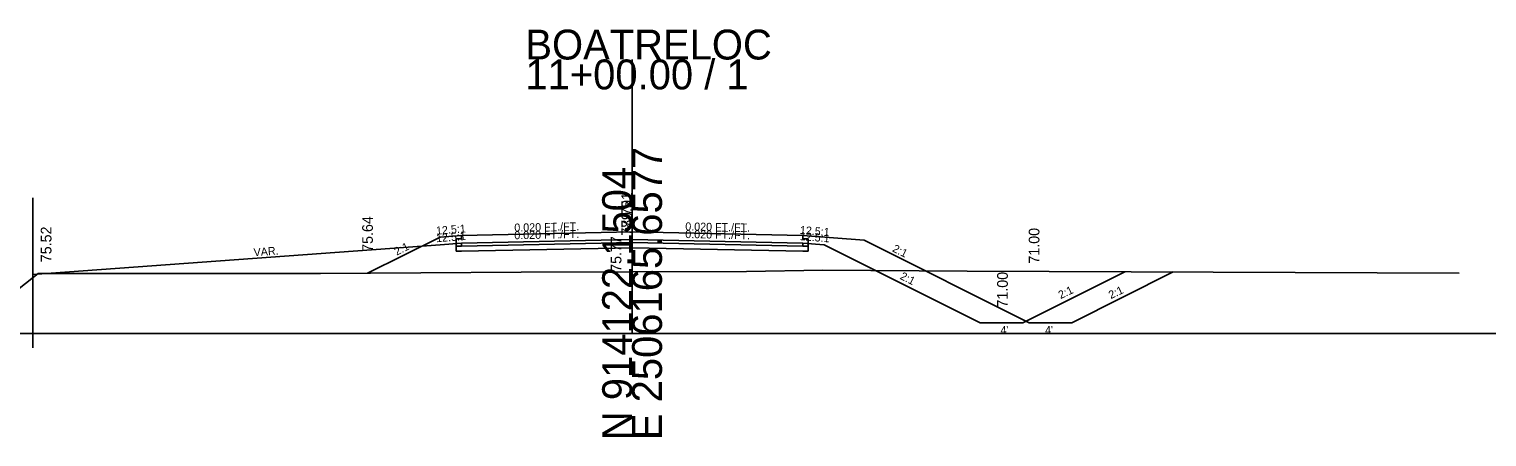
# Model space of a CAD drawing. Extents: x -26 to 403, y -10 to 2549.
# Drawn here: x 143.5 to 280.1, y 490.3 to 528.5 of the extents above; entities that cross this region are included whole.
import ezdxf

# ---------------------------------------------------------------- set-up
doc = ezdxf.new("R2010")
doc.units = 0
for name, color, linetype in [('RD_GPK_XS_Cell', 7, 'Continuous'), ('RD_Sketch9', 7, 'Continuous'), ('RD_XS_EarthShd', 7, 'Continuous'), ('RD_XS_ExGround', 7, 'Continuous'), ('RD_XS_Pave', 7, 'Continuous'), ('RD_XS_PaveOvlay', 7, 'Continuous'), ('RD_XS_TieSlope', 7, 'Continuous'), ('RD_XS_TX_Elev_EX', 7, 'Continuous'), ('RD_XS_TX_Elev_PR', 7, 'Continuous'), ('RD_XS_TX_ShdSlope', 7, 'Continuous'), ('RD_XS_TX_Slope', 7, 'Continuous')]:
    doc.layers.add(name, color=color, linetype=linetype)

msp = doc.modelspace()

# ---------------------------------------------------------------- linework, layer by layer
at = {"layer": 'RD_GPK_XS_Cell'}
for p, q in [((200, 500), (200, 525.67)), ((0, 500), (200, 500)), ((200, 500), (400, 500))]:
    msp.add_line(p, q, dxfattribs=at)
at = {"layer": 'RD_Sketch9'}
for p, q in [((182, 509.03), (175.21, 505.64)), ((184, 509.19), (182, 509.03)), ((183.5, 508.85), (184, 508.86)), ((183.5, 508.18), (183.5, 508.85)), ((184, 508.19), (183.5, 508.18)), ((184, 509.19), (200, 509.51)), ((184, 508.86), (184, 509.19)), ((184, 508.19), (200, 508.51)), ((200, 509.51), (216, 509.19)), ((200, 508.51), (216, 508.19)), ((216, 508.86), (216, 509.19)), ((216, 509.19), (221.74, 508.73)), ((216.5, 508.85), (216, 508.86)), ((216, 508.19), (216.5, 508.18)), ((216.5, 508.18), (216.5, 508.85)), ((221.74, 508.73), (237.2, 501)), ((250.71, 505.76), (241.2, 501)), ((237.2, 501), (241.2, 501))]:
    msp.add_line(p, q, dxfattribs=at)
at = {"layer": 'RD_XS_EarthShd'}
for p, q in [((184, 508.47), (182, 508.31)), ((216, 508.47), (218, 508.31))]:
    msp.add_line(p, q, dxfattribs=at)
at = {"layer": 'RD_XS_ExGround'}
for p, q in [((141.39, 503.28), (144.35, 505.6)), ((144.35, 505.6), (158.25, 505.6)), ((158.25, 505.6), (164.72, 505.6)), ((164.72, 505.6), (167.77, 505.61)), ((167.77, 505.61), (170.79, 505.61)), ((170.79, 505.61), (189.59, 505.73)), ((189.59, 505.73), (200, 505.77)), ((200, 505.77), (210.71, 505.81)), ((210.71, 505.81), (217.87, 505.92)), ((217.87, 505.92), (231.41, 505.84)), ((231.41, 505.84), (277.51, 505.64))]:
    msp.add_line(p, q, dxfattribs=at)
at = {"layer": 'RD_XS_Pave'}
for p, q in [((183.5, 508.18), (184, 508.19)), ((183.5, 507.7), (183.5, 508.18)), ((184, 508.19), (184, 508.47)), ((216, 508.19), (216, 508.47)), ((216.5, 508.18), (216, 508.19)), ((216.5, 507.7), (216.5, 508.18)), ((184, 507.71), (183.5, 507.7)), ((184, 507.71), (200, 508.03)), ((200, 508.03), (216, 507.71)), ((216, 507.71), (216.5, 507.7))]:
    msp.add_line(p, q, dxfattribs=at)
at = {"layer": 'RD_XS_PaveOvlay'}
for p, q in [((184, 508.47), (200, 508.79)), ((200, 508.79), (216, 508.47))]:
    msp.add_line(p, q, dxfattribs=at)
at = {"layer": 'RD_XS_TieSlope'}
for p, q in [((143.84, 498.64), (143.84, 512.72)), ((182, 508.31), (143.84, 505.52)), ((218, 508.31), (232.63, 501)), ((246.18, 505.77), (236.63, 501)), ((232.63, 501), (236.63, 501))]:
    msp.add_line(p, q, dxfattribs=at)

# ---------------------------------------------------------------- texts
at = {"layer": 'RD_GPK_XS_Cell'}
for s, p in [('BOATRELOC', (190, 525.67)), ('11+00.00 / 1', (190, 522.87))]:
    msp.add_text(s, height=2.8, dxfattribs=at).set_placement(p)
for s, p in [('E 2506165.6577', (202.8, 490)), ('N 914122.1504', (200, 490))]:
    msp.add_text(s, height=2.8, rotation=90, dxfattribs=at).set_placement(p)
at = {"layer": 'RD_Sketch9'}
for s, height, rotation, p in [(' 79.51', 1, 90, (200, 509.51)), (' 79.51', 1, 90, (200, 509.51)), ('75.64', 1, 90, (175.71, 507.64)), ('12.5:1', 0.75, 4.5739, (181.66, 509.25)), ('0.020 FT./FT.', 0.75, 1.1458, (188.97, 509.54)), ('0.020 FT./FT.', 0.75, 358.8542, (204.98, 509.66)), ('12.5:1', 0.75, 355.4261, (215.7, 509.33)), ('71.00', 1, 90, (238.17, 506.54)), ('2:1', 0.75, 26.5651, (177.94, 507.28)), ('2:1', 0.75, 333.4349, (224.33, 507.71)), ('2:1', 0.75, 25.4593, (244.87, 503.21)), ("4'", 0.75, 2.665, (238.72, 499.92))]:
    msp.add_text(s, height=height, rotation=rotation, dxfattribs=at).set_placement(p)
at = {"layer": 'RD_XS_TX_Elev_EX'}
msp.add_text('75.77', height=1, rotation=90, dxfattribs=at).set_placement((199, 505.77))
at = {"layer": 'RD_XS_TX_Elev_PR'}
for s, p in [(' 78.79', (200, 508.79)), ('75.52', (145.59, 506.67)), ('71.00', (235.21, 502.42))]:
    msp.add_text(s, height=1, rotation=90, dxfattribs=at).set_placement(p)
at = {"layer": 'RD_XS_TX_ShdSlope'}
for rotation, p in [(4.5739, (181.66, 508.54)), (355.4261, (215.7, 508.75))]:
    msp.add_text('12.5:1', height=0.75, rotation=rotation, dxfattribs=at).set_placement(p)
at = {"layer": 'RD_XS_TX_Slope'}
for s, rotation, p in [('0.020 FT./FT.', 1.1458, (188.97, 508.82)), ('0.020 FT./FT.', 358.8542, (204.98, 508.94)), ('VAR.', 4.3605, (164.56, 507.22)), ('2:1', 333.4349, (225.04, 505.13)), ('2:1', 25.4593, (240.16, 503.21)), ("4'", 2.665, (234.54, 499.92))]:
    msp.add_text(s, height=0.75, rotation=rotation, dxfattribs=at).set_placement(p)

doc.saveas('drawing.dxf')
